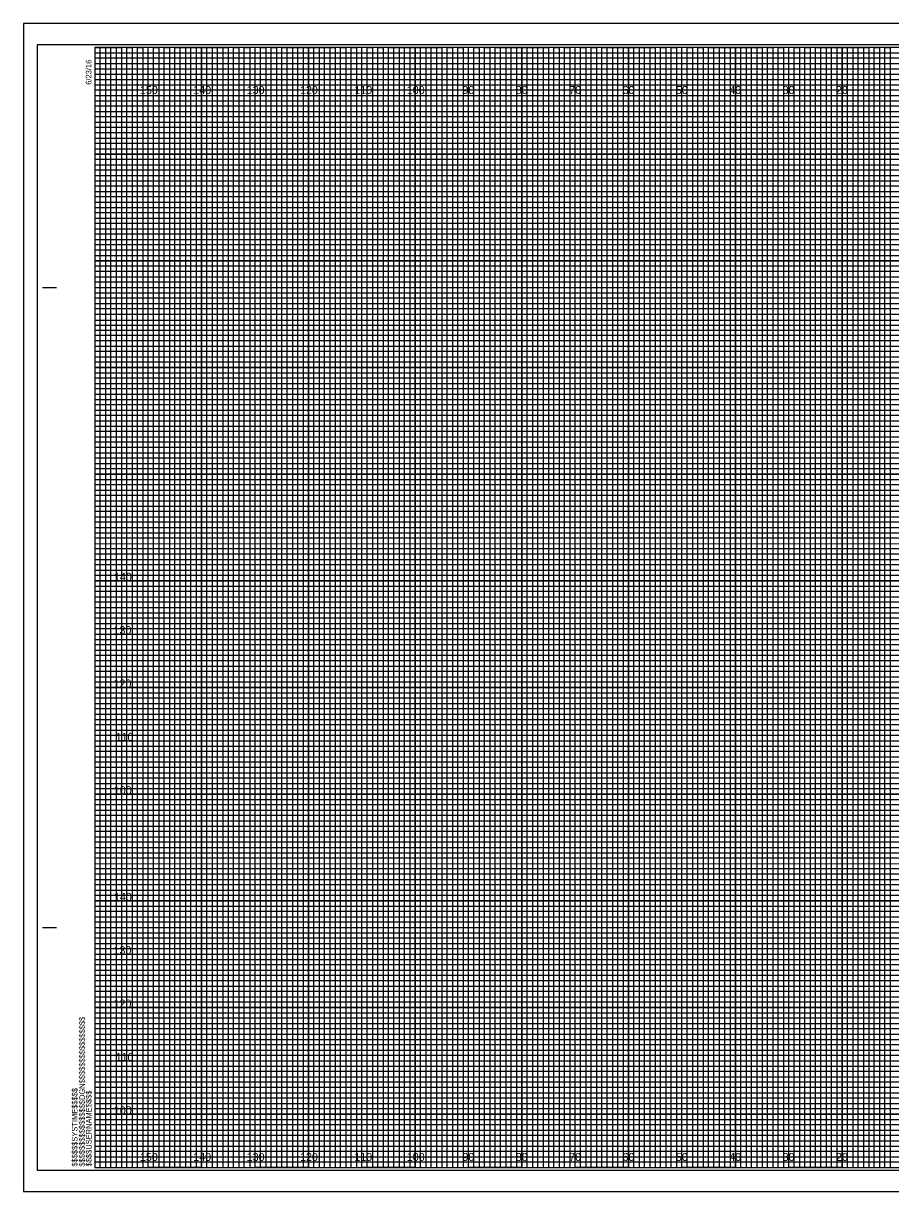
# Model space of a CAD drawing. Extents: x -13 to 323, y -5 to 2634.
# Drawn here: x -13.4 to 149.1, y 2415.5 to 2634.5 of the extents above; entities that cross this region are included whole.
import ezdxf

# ---------------------------------------------------------------- set-up
doc = ezdxf.new("R2010")
doc.units = 0
for name, color, linetype in [('Exist Cross Section Cell', 7, 'Continuous'), ('Exist XS Center Line Elevation Label', 7, 'Continuous'), ('Exist XS Ground Line', 7, 'Continuous'), ('Prop CMT Pvmt Course 1 Wedge', 7, 'Continuous'), ('Prop CMT Pvmt Course 2', 7, 'Continuous'), ('Prop CMT Pvmt Course 2 Wedge', 7, 'Continuous'), ('Prop CMT Pvmt Course 3', 7, 'Continuous'), ('Prop CMT Shld Paved Course 1', 7, 'Continuous'), ('Prop CMT Shld Paved Course 2', 7, 'Continuous'), ('Prop CMT Subgrade Earthwork', 7, 'Continuous'), ('Scratch_Level_0', 7, 'Continuous')]:
    doc.layers.add(name, color=color, linetype=linetype)

msp = doc.modelspace()

# ---------------------------------------------------------------- linework, layer by layer
at = {"layer": 'Exist XS Center Line Elevation Label'}
for points in [[(0, 2630), (5, 2630), (5, 2420), (15, 2420), (15, 2630), (25, 2630), (25, 2420), (35, 2420), (35, 2630), (45, 2630), (45, 2420), (55, 2420), (55, 2630), (65, 2630), (65, 2420), (75, 2420), (75, 2630), (85, 2630), (85, 2420), (95, 2420), (95, 2630), (105, 2630), (105, 2420), (115, 2420), (115, 2630), (125, 2630), (125, 2420), (135, 2420), (135, 2630), (145, 2630), (145, 2420), (155, 2420)], [(0, 2625), (275, 2625)], [(0, 2605), (320, 2605), (320, 2615), (0, 2615)], [(0, 2585), (320, 2585), (320, 2595), (0, 2595)], [(0, 2565), (320, 2565), (320, 2575), (0, 2575)], [(0, 2545), (320, 2545), (320, 2555), (0, 2555)], [(0, 2525), (320, 2525), (320, 2535), (0, 2535)], [(0, 2505), (320, 2505), (320, 2515), (0, 2515)], [(0, 2485), (320, 2485), (320, 2495), (0, 2495)], [(0, 2465), (320, 2465), (320, 2475), (0, 2475)], [(0, 2445), (320, 2445), (320, 2455), (0, 2455)], [(0, 2425), (320, 2425), (320, 2435), (0, 2435)]]:
    msp.add_lwpolyline(points, dxfattribs=at)
at = {"layer": 'Exist XS Ground Line'}
for p, q in [((10, 2630), (0, 2630)), ((10, 2420), (10, 2630)), ((30, 2630), (20, 2630)), ((20, 2630), (20, 2420)), ((30, 2420), (30, 2630)), ((50, 2630), (40, 2630)), ((40, 2630), (40, 2420)), ((50, 2420), (50, 2630)), ((70, 2630), (60, 2630)), ((60, 2630), (60, 2420)), ((70, 2420), (70, 2630)), ((90, 2630), (80, 2630)), ((80, 2630), (80, 2420)), ((90, 2420), (90, 2630)), ((110, 2630), (100, 2630)), ((100, 2630), (100, 2420)), ((110, 2420), (110, 2630)), ((130, 2630), (120, 2630)), ((120, 2630), (120, 2420)), ((130, 2420), (130, 2630)), ((150, 2630), (140, 2630)), ((140, 2630), (140, 2420)), ((20, 2420), (10, 2420)), ((40, 2420), (30, 2420)), ((60, 2420), (50, 2420)), ((80, 2420), (70, 2420)), ((100, 2420), (90, 2420)), ((120, 2420), (110, 2420)), ((140, 2420), (130, 2420))]:
    msp.add_line(p, q, dxfattribs=at)
for points in [[(0, 2620), (320, 2620), (320, 2610), (0, 2610)], [(0, 2600), (320, 2600), (320, 2590), (0, 2590)], [(0, 2580), (320, 2580), (320, 2570), (0, 2570)], [(0, 2560), (320, 2560), (320, 2550), (0, 2550)], [(0, 2540), (320, 2540), (320, 2530), (0, 2530)], [(0, 2520), (320, 2520), (320, 2510), (0, 2510)], [(0, 2500), (320, 2500), (320, 2490), (0, 2490)], [(0, 2480), (320, 2480), (320, 2470), (0, 2470)], [(0, 2460), (320, 2460), (320, 2450), (0, 2450)], [(0, 2440), (320, 2440), (320, 2430), (0, 2430)]]:
    msp.add_lwpolyline(points, dxfattribs=at)
at = {"layer": 'Prop CMT Pvmt Course 1 Wedge'}
for p, q in [((323.3, 2634.5), (-13.4, 2634.5)), ((-13.4, 2634.5), (-13.4, 2415.5)), ((-13.4, 2415.5), (323.3, 2415.5))]:
    msp.add_line(p, q, dxfattribs=at)
at = {"layer": 'Prop CMT Pvmt Course 2'}
msp.add_lwpolyline([(-13.4, 2415.5), (323.3, 2415.5), (323.3, 2634.5), (-13.4, 2634.5)], close=True, dxfattribs=at)
at = {"layer": 'Prop CMT Pvmt Course 3'}
msp.add_lwpolyline([(-10.8, 2419.5), (322.4, 2419.5), (322.4, 2630.5), (-10.8, 2630.5)], close=True, dxfattribs=at)
at = {"layer": 'Prop CMT Shld Paved Course 1'}
for p, q in [((-9.8, 2585), (-7.3, 2585)), ((-9.7, 2585), (-7.2, 2585)), ((-9.8, 2465), (-7.3, 2465)), ((-9.7, 2465), (-7.2, 2465)), ((0, 2420), (0, 2420)), ((0, 2420), (0, 2420)), ((0, 2420), (0, 2420)), ((0, 2420), (0, 2420)), ((0, 2420), (0, 2420)), ((0, 2420), (0, 2420)), ((0, 2420), (0, 2420))]:
    msp.add_line(p, q, dxfattribs=at)
msp.add_lwpolyline([(320, 2630), (0, 2630), (0, 2420), (320, 2420)], close=True, dxfattribs=at)
at = {"layer": 'Prop CMT Shld Paved Course 2'}
for points in [[(0, 2420), (1, 2420), (1, 2630), (2, 2630), (2, 2420)], [(2, 2420), (3, 2420), (3, 2630), (4, 2630), (4, 2420)], [(5, 2420), (6, 2420), (6, 2630), (7, 2630), (7, 2420)], [(7, 2420), (8, 2420), (8, 2630), (9, 2630), (9, 2420)], [(10, 2420), (11, 2420), (11, 2630), (12, 2630), (12, 2420)], [(12, 2420), (13, 2420), (13, 2630), (14, 2630), (14, 2420)], [(15, 2420), (16, 2420), (16, 2630), (17, 2630), (17, 2420)], [(17, 2420), (18, 2420), (18, 2630), (19, 2630), (19, 2420)], [(20, 2420), (21, 2420), (21, 2630), (22, 2630), (22, 2420)], [(22, 2420), (23, 2420), (23, 2630), (24, 2630), (24, 2420)], [(25, 2420), (26, 2420), (26, 2630), (27, 2630), (27, 2420)], [(27, 2420), (28, 2420), (28, 2630), (29, 2630), (29, 2420)], [(30, 2420), (31, 2420), (31, 2630), (32, 2630), (32, 2420)], [(32, 2420), (33, 2420), (33, 2630), (34, 2630), (34, 2420)], [(35, 2420), (36, 2420), (36, 2630), (37, 2630), (37, 2420)], [(37, 2420), (38, 2420), (38, 2630), (39, 2630), (39, 2420)], [(40, 2420), (41, 2420), (41, 2630), (42, 2630), (42, 2420)], [(42, 2420), (43, 2420), (43, 2630), (44, 2630), (44, 2420)], [(45, 2420), (46, 2420), (46, 2630), (47, 2630), (47, 2420)], [(47, 2420), (48, 2420), (48, 2630), (49, 2630), (49, 2420)], [(50, 2420), (51, 2420), (51, 2630), (52, 2630), (52, 2420)], [(52, 2420), (53, 2420), (53, 2630), (54, 2630), (54, 2420)], [(55, 2420), (56, 2420), (56, 2630), (57, 2630), (57, 2420)], [(57, 2420), (58, 2420), (58, 2630), (59, 2630), (59, 2420)], [(60, 2420), (61, 2420), (61, 2630), (62, 2630), (62, 2420)], [(62, 2420), (63, 2420), (63, 2630), (64, 2630), (64, 2420)], [(65, 2420), (66, 2420), (66, 2630), (67, 2630), (67, 2420)], [(67, 2420), (68, 2420), (68, 2630), (69, 2630), (69, 2420)], [(70, 2420), (71, 2420), (71, 2630), (72, 2630), (72, 2420)], [(72, 2420), (73, 2420), (73, 2630), (74, 2630), (74, 2420)], [(75, 2420), (76, 2420), (76, 2630), (77, 2630), (77, 2420)], [(77, 2420), (78, 2420), (78, 2630), (79, 2630), (79, 2420)], [(80, 2420), (81, 2420), (81, 2630), (82, 2630), (82, 2420)], [(82, 2420), (83, 2420), (83, 2630), (84, 2630), (84, 2420)], [(85, 2420), (86, 2420), (86, 2630), (87, 2630), (87, 2420)], [(87, 2420), (88, 2420), (88, 2630), (89, 2630), (89, 2420)], [(90, 2420), (91, 2420), (91, 2630), (92, 2630), (92, 2420)], [(92, 2420), (93, 2420), (93, 2630), (94, 2630), (94, 2420)], [(95, 2420), (96, 2420), (96, 2630), (97, 2630), (97, 2420)], [(97, 2420), (98, 2420), (98, 2630), (99, 2630), (99, 2420)], [(100, 2420), (101, 2420), (101, 2630), (102, 2630), (102, 2420)], [(102, 2420), (103, 2420), (103, 2630), (104, 2630), (104, 2420)], [(105, 2420), (106, 2420), (106, 2630), (107, 2630), (107, 2420)], [(107, 2420), (108, 2420), (108, 2630), (109, 2630), (109, 2420)], [(110, 2420), (111, 2420), (111, 2630), (112, 2630), (112, 2420)], [(112, 2420), (113, 2420), (113, 2630), (114, 2630), (114, 2420)], [(115, 2420), (116, 2420), (116, 2630), (117, 2630), (117, 2420)], [(117, 2420), (118, 2420), (118, 2630), (119, 2630), (119, 2420)], [(120, 2420), (121, 2420), (121, 2630), (122, 2630), (122, 2420)], [(122, 2420), (123, 2420), (123, 2630), (124, 2630), (124, 2420)], [(125, 2420), (126, 2420), (126, 2630), (127, 2630), (127, 2420)], [(127, 2420), (128, 2420), (128, 2630), (129, 2630), (129, 2420)], [(130, 2420), (131, 2420), (131, 2630), (132, 2630), (132, 2420)], [(132, 2420), (133, 2420), (133, 2630), (134, 2630), (134, 2420)], [(135, 2420), (136, 2420), (136, 2630), (137, 2630), (137, 2420)], [(137, 2420), (138, 2420), (138, 2630), (139, 2630), (139, 2420)], [(140, 2420), (141, 2420), (141, 2630), (142, 2630), (142, 2420)], [(142, 2420), (143, 2420), (143, 2630), (144, 2630), (144, 2420)], [(145, 2420), (146, 2420), (146, 2630), (147, 2630), (147, 2420)], [(147, 2420), (148, 2420), (148, 2630), (149, 2630), (149, 2420)]]:
    msp.add_lwpolyline(points, dxfattribs=at)
at = {"layer": 'Prop CMT Subgrade Earthwork'}
for p, q in [((10, 2420), (10, 2630)), ((20, 2420), (20, 2630)), ((30, 2420), (30, 2630)), ((40, 2420), (40, 2630)), ((50, 2420), (50, 2630)), ((60, 2420), (60, 2630)), ((70, 2420), (70, 2630)), ((80, 2420), (80, 2630)), ((90, 2420), (90, 2630)), ((100, 2420), (100, 2630)), ((110, 2420), (110, 2630)), ((120, 2420), (120, 2630)), ((130, 2420), (130, 2630)), ((140, 2420), (140, 2630)), ((0, 2620), (320, 2620)), ((0, 2610), (320, 2610)), ((0, 2600), (320, 2600)), ((0, 2590), (320, 2590)), ((0, 2580), (320, 2580)), ((0, 2570), (320, 2570)), ((0, 2560), (320, 2560)), ((0, 2550), (320, 2550)), ((0, 2540), (320, 2540)), ((0, 2530), (320, 2530)), ((0, 2520), (320, 2520)), ((0, 2510), (320, 2510)), ((0, 2500), (320, 2500)), ((0, 2490), (320, 2490)), ((0, 2480), (320, 2480)), ((0, 2470), (320, 2470)), ((0, 2460), (320, 2460)), ((0, 2450), (320, 2450)), ((0, 2440), (320, 2440)), ((0, 2430), (320, 2430))]:
    msp.add_line(p, q, dxfattribs=at)
at = {"layer": 'Scratch_Level_0'}
for p, q in [((0, 2629), (260, 2629)), ((260, 2627.98), (0, 2627.98)), ((0, 2627.98), (0, 2627)), ((0, 2627), (260, 2627)), ((260, 2625.89), (0, 2625.89)), ((0, 2625.89), (0, 2624)), ((0, 2624), (320, 2624))]:
    msp.add_line(p, q, dxfattribs=at)
for points in [[(0, 2623), (270, 2623), (320, 2623), (320, 2622), (0, 2622)], [(0, 2621), (320, 2621), (320, 2619), (0, 2619)], [(0, 2618), (320, 2618), (320, 2617), (0, 2616.98)], [(0, 2616), (320, 2616), (320, 2614), (0, 2614)], [(0, 2613), (320, 2613), (320, 2612), (0, 2612)], [(0, 2611), (320, 2611), (320, 2609), (0, 2609)], [(0, 2608), (320, 2608), (320, 2607), (0, 2607)], [(0, 2606), (320, 2606), (320, 2604), (0, 2604)], [(0, 2603), (320, 2603), (320, 2602), (0, 2602)], [(0, 2601), (320, 2601), (320, 2599), (0, 2599)], [(0, 2598), (320, 2598), (320, 2597), (0, 2597)], [(0, 2596), (320, 2596), (320, 2593.95), (320, 2593), (320, 2592), (0, 2592)], [(0, 2594), (320, 2594), (320, 2593), (0, 2593)], [(0, 2591), (320, 2591), (320, 2589), (0, 2589.03)], [(0, 2589.03), (320, 2589), (320, 2588), (0, 2588)], [(0, 2587), (320, 2587), (320, 2586), (0, 2586)], [(0, 2584), (320, 2584), (320, 2583), (0, 2583)], [(0, 2582), (320, 2582), (320, 2581), (0, 2581)], [(-0.07, 2578.89), (320, 2578.89), (320, 2577.88), (-0.07, 2577.88)], [(0, 2577), (320, 2577), (320, 2576), (0, 2576)], [(0, 2574), (320, 2574), (320, 2573), (0, 2573)], [(0, 2572), (320, 2572), (320, 2571), (0, 2571)], [(0, 2569), (320, 2569), (320, 2568), (0, 2568)], [(0, 2567), (320, 2567), (320, 2566), (0, 2566)], [(0, 2564), (320, 2564), (320, 2563), (0, 2563)], [(0, 2562), (320, 2562), (320, 2561), (0, 2561)], [(0, 2559), (320, 2559), (319.99, 2557.98), (0, 2558)], [(0, 2557), (320, 2557), (320, 2556), (0, 2556)], [(0, 2554), (320, 2554), (320, 2553), (0, 2553)], [(0, 2552), (320, 2552), (320, 2551), (0, 2551)], [(0, 2549), (320, 2549), (320, 2548), (0, 2548)], [(0, 2547), (320, 2547), (320, 2546), (0, 2546)], [(0, 2544), (320, 2544), (320, 2543), (0, 2543)], [(0, 2542), (320, 2542), (320, 2541), (0, 2541)], [(0, 2539), (320, 2539), (320, 2538), (0, 2538)], [(0, 2536.99), (320.07, 2536.91), (320, 2536), (0, 2536)], [(0, 2534), (320, 2534), (320, 2533), (0, 2533)], [(0, 2532), (320, 2532), (320, 2531), (0, 2531)], [(0, 2529), (320, 2529), (320, 2528), (0, 2528)], [(0, 2527), (320, 2527), (320, 2526), (0, 2526)], [(0, 2524), (320, 2524), (320, 2523), (0, 2523)], [(0, 2522), (320, 2522), (320, 2521), (0, 2521)], [(0, 2519), (320, 2519), (320, 2518), (0, 2518)], [(0, 2517), (320, 2517), (320, 2516), (0, 2516)], [(0, 2514), (320, 2514), (320, 2513), (0, 2513)], [(0, 2512), (320, 2512), (320, 2511), (0, 2511)], [(0, 2509), (320, 2509), (320, 2508), (0, 2508)], [(0, 2507), (320, 2507), (320, 2506), (0, 2506)], [(0, 2504), (320, 2504), (320, 2503), (0, 2503)], [(0, 2502), (320, 2502), (320, 2501), (0, 2501)], [(0, 2499), (320, 2499), (319.99, 2497.98), (0, 2498)], [(0, 2497), (320, 2497), (320, 2496), (0, 2496)], [(0, 2494), (320, 2494), (320, 2493), (0, 2493)], [(0, 2492), (320, 2492), (320, 2491), (0, 2491)], [(0, 2489), (320, 2489), (320, 2488), (0, 2488)], [(0, 2487), (320, 2487), (320, 2486), (0, 2486)], [(0, 2484), (320, 2484), (320, 2483), (0, 2483)], [(0, 2482), (320, 2482), (320, 2481), (0, 2481)], [(0, 2479), (320, 2479), (320, 2478), (0, 2478)], [(0, 2476.99), (320.07, 2476.91), (320, 2476), (0, 2476)], [(0, 2474), (320, 2474), (320, 2473), (0, 2473)], [(0, 2472), (320, 2472), (320, 2471), (0, 2471)], [(0, 2469), (320, 2469), (320, 2468), (0, 2468)], [(0, 2467), (320, 2467), (320, 2466), (0, 2466)], [(0, 2464), (320, 2464), (320, 2463), (0, 2463)], [(0, 2462), (320, 2462), (320, 2461), (0, 2461)], [(0, 2459), (320, 2459), (320, 2458), (0, 2458)], [(0, 2457), (320, 2457), (320, 2456), (0, 2456)], [(0, 2454), (320, 2454), (320, 2453), (0, 2453)], [(0, 2452), (320, 2452), (320, 2451), (0, 2451)], [(0, 2449), (320, 2449), (320, 2448), (0, 2448)], [(0, 2447), (320, 2447), (320, 2446), (0, 2446)], [(0, 2444), (320, 2444), (320, 2443), (0, 2443)], [(0, 2442), (320, 2442), (320, 2441), (0, 2441)], [(0, 2439), (320, 2439), (320, 2438), (0, 2438)], [(0, 2437), (320, 2437), (320, 2436), (0, 2436)], [(0, 2434), (320, 2434), (320, 2433), (0, 2433)], [(0, 2432), (320, 2432), (320, 2431), (0, 2431)], [(0, 2429), (320, 2429), (320, 2428), (0, 2428)], [(0, 2427), (320, 2427), (320, 2426), (0, 2426)], [(0, 2424), (320, 2424), (320, 2423), (0, 2423)], [(0, 2422), (320, 2422), (320, 2421), (0, 2421)]]:
    msp.add_lwpolyline(points, dxfattribs=at)

# ---------------------------------------------------------------- texts
at = {"layer": 'Exist Cross Section Cell'}
for s, p in [('150', (8.44, 2621.25)), ('140', (18.44, 2621.25)), ('130', (28.44, 2621.25)), ('120', (38.44, 2621.25)), ('110', (48.62, 2621.25)), ('100', (58.44, 2621.25)), ('90', (68.86, 2621.25)), ('80', (78.86, 2621.25)), ('70', (88.86, 2621.25)), ('60', (98.86, 2621.25)), ('50', (108.86, 2621.25)), ('40', (118.86, 2621.25)), ('30', (128.86, 2621.25)), ('20', (138.86, 2621.25)), ('150', (8.44, 2421.25)), ('140', (18.44, 2421.25)), ('130', (28.44, 2421.25)), ('120', (38.44, 2421.25)), ('110', (48.62, 2421.25)), ('100', (58.44, 2421.25)), ('90', (68.86, 2421.25)), ('80', (78.86, 2421.25)), ('70', (88.86, 2421.25)), ('60', (98.86, 2421.25)), ('50', (108.86, 2421.25)), ('40', (118.86, 2421.25)), ('30', (128.86, 2421.25)), ('20', (138.86, 2421.25))]:
    msp.add_text(s, height=1.5, dxfattribs=at).set_placement(p)
at = {"layer": 'Prop CMT Pvmt Course 2 Wedge'}
for s, p in [('140', (3.57, 2530)), ('130', (3.49, 2520)), ('120', (3.5, 2510)), ('110', (3.88, 2500)), ('100', (3.55, 2490)), ('140', (3.57, 2470)), ('130', (3.49, 2460)), ('120', (3.5, 2450)), ('110', (3.88, 2440)), ('100', (3.55, 2430))]:
    msp.add_text(s, height=1.5, dxfattribs=at).set_placement(p)
at = {"layer": 'Prop CMT Shld Paved Course 1'}
for s, p in [('6/23/16', (-0.65, 2623)), ('$$$$$$$$$$$$$$$$DGN$$$$$$$$$$$$$$$$', (-1.88, 2420.18)), ('$$$$$$SYSTIME$$$$$', (-3.26, 2420.18)), ('$$$$USERNAME$$$$', (-0.62, 2420.23))]:
    msp.add_text(s, height=1.05, rotation=90, dxfattribs=at).set_placement(p)

doc.saveas('drawing.dxf')
